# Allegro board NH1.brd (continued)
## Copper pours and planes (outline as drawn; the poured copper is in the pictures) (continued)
GND on TOP (solid shape): 11.15,53.3 11.2,53.27 11.27,53.21 11.48,53.01 11.5,53 11.63,52.85 11.57,52.66 11.53,52.63 11.53,52.35 11.61,52.27 11.61,52.11 11.5,52 11.5,51.66 12.14,51.02 12.17,51.01 12.24,50.96 12.28,50.89 12.3,50.86 12.3,50.85 12.54,50.61 12.58,50.55 12.59,50.49 12.58,50.43 12.55,50.38 12.54,50.37 12.49,50.34 12.44,50.33 12.38,50.32 12.17,50.12 12.17,50.04 12.11,49.96 12,49.99 11.96,50.03 11.96,50.29 12.02,50.59 11.76,50.77 11.22,50.77 11.05,50.93 11.01,51 10.97,51.06 10.93,51.14 10.97,51.21 11.08,51.48 10.93,51.72 10.93,51.72 10.74,51.91 10.74,52.4 10.85,52.52 10.87,52.52 11.07,52.78 10.92,53.08 10.93,53.11 10.94,53.19 10.97,53.24 11,53.27 11.05,53.3 11.1,53.31
GND on TOP (solid shape): 14.01,56.49 14.13,56.52 14.13,56.34 14.46,56.01 14.46,56 14.58,55.87 14.75,55.82 14.78,55.8 14.8,55.77 14.8,55.13 14.82,55.02 14.88,54.93 15.12,54.69 15.12,54.68 15.22,54.54 15.38,54.49 15.45,54.46 15.48,54.39 15.48,53.67 15.53,53.64 15.62,53.47 15.53,53.3 15.52,53.29 15.21,52.98 15.15,52.98 15.1,52.97 15.03,52.97 14.97,52.98 14.88,52.89 14.65,52.89 14.65,54.52 14.63,54.55 14.58,54.63 14.49,54.68 14.45,54.72 14.19,54.72 13.8,54.33 13.72,54.3 13.65,54.34 13.6,54.38 13.53,54.42 13.4,54.55 13.4,54.59 13.34,54.61 13.29,54.66 13.24,54.7 13.22,54.74 12.96,55 12.93,55.06 12.91,55.12 12.91,55.16 12.62,55.45 12.6,55.52 12.62,55.59 12.65,55.62 12.66,55.64 12.74,55.69 12.82,55.66 13.05,55.44 13.79,55.44 14.03,55.68 14.03,55.91 13.87,56.07 13.73,56.07 13.73,56.15 13.81,56.23 13.82,56.24 13.93,56.31 13.98,56.43
GND on TOP (solid shape): 26.25,63.36 26.26,63.36 26.37,63.25 27.25,63.25 27.41,63.1 27.41,62.97 27.46,62.82 27.61,62.77 27.91,62.77 27.95,62.77 27.99,62.78 28.09,62.78 28.14,62.69 28.14,62.08 27.55,61.5 27.54,61.49 27.38,61.41 27.29,61.25 27.29,61.24 27.22,61.16 27.15,61.13 27.08,61.16 26.58,61.04 26.9,60.64 26.92,60.64 27.02,60.54 27.02,60.2 26.92,59.95 27.02,59.7 27.02,59.54 26.92,59.44 26.01,59.44 25.84,59.61 25.84,59.63 25.76,59.87 25.55,59.99 25.29,59.94 25.14,59.73 25.14,59.58 25.19,59.44 25.19,59.34 25.11,59.29 24.53,59.29 24.48,59.34 24.48,60.3 24.63,60.46 25.13,60.46 25.77,61.1 25.77,61.82 26.09,62.13 26.26,62.13 26.4,62.19 26.46,62.33 26.46,62.61 26.45,62.66 26.44,62.7 26.36,62.79 26.26,62.82 25.96,62.82 25.93,62.81 25.9,62.81 25.48,62.81 25.4,62.9 25.4,63.35 25.7,63.66 25.95,63.66
GND on TOP (solid shape): 14.01,56.49 14.09,56.52 14.15,56.49 14.19,56.43 14.21,56.35 14.25,56.29 14.44,56.1 14.44,56.09 14.54,55.89 14.75,55.82 14.82,55.79 14.85,55.72 14.85,55.13 14.86,55.04 14.91,54.97 15.1,54.78 15.1,54.76 15.19,54.57 15.38,54.49 15.45,54.46 15.48,54.39 15.48,53.67 15.53,53.64 15.62,53.47 15.53,53.3 15.52,53.29 15.21,52.98 15.16,52.98 15.14,52.96 14.95,52.97 14.88,52.89 14.7,52.89 14.67,52.91 14.65,52.94 14.65,54.52 14.63,54.55 14.63,54.56 14.58,54.63 14.5,54.68 14.49,54.68 14.45,54.72 14.19,54.72 13.8,54.33 13.72,54.3 13.65,54.34 13.56,54.41 13.46,54.44 13.44,54.44 13.41,54.47 13.4,54.48 13.4,54.5 13.4,54.58 13.32,54.62 13.27,54.66 13.23,54.72 13.22,54.74 12.96,55 12.91,55.06 12.91,55.16 12.59,55.49 12.56,55.56 12.59,55.63 12.63,55.69 12.65,55.77 12.67,55.8 12.71,55.81 12.75,55.81 12.93,55.63 13.07,55.49 13.77,55.49 13.91,55.63 13.97,55.85 13.8,56.01 13.75,56.05 13.73,56.12 13.73,56.13 13.75,56.19 13.8,56.23 13.92,56.3 13.98,56.43
GND on TOP (solid shape): outline of 94 points within 7.09,58.43 10.99,66.74
GND on TOP (solid shape): outline of 268 points within 3.53,76.15 6.64,78.59
GND on TOP (solid shape): outline of 133 points within 5.91,54.29 10.65,57.14
GND on TOP (solid shape): outline of 687 points within 22.54,83.91 32.99,91.29
GND on TOP (solid shape): outline of 1494 points within 16.38,51.67 29.68,58.47
GND on TOP (solid shape): outline of 4116 points within 0.51,0.51 32.99,91.29
GND on TOP (solid shape): outline of 4131 points within 2.82,41.79 22.4,52.79
GND on BOTTOM (solid shape): 11.63,28.56 11.63,28.26 11.54,28.17 10.26,28.17 10.1,28.33 10.1,28.81 10.18,28.88 10.2,28.89 10.27,28.9 10.34,28.94 11.25,28.94
GND on BOTTOM (solid shape): 6.11,60.81 6.18,60.9 6.29,60.88 6.44,60.73 6.5,60.73 6.59,60.66 6.57,60.55 6.3,60.29 6.3,59.09 6.31,59.05 6.32,59.01 6.32,57.82 6.25,57.74 6.22,57.73 6.15,57.74 6.09,57.73 6,57.75 5.96,57.83 5.96,58.35 6.11,58.51
GND on BOTTOM (solid shape): 8.75,31.83 8.75,31.37 8.65,31.27 8.2,31.27 8.16,31.23 8.14,31.23 7.97,31.07 7.97,31.05 7.54,30.61 7.23,30.61 7.23,30.61 6.97,30.61 6.61,30.26 6.61,29 6.64,28.97 6.64,28.14 7.06,27.73 7.06,26.37 6.92,26.24 6.36,26.24 6.32,26.25 6.29,26.26 6.3,26.44 6.22,26.59 6.21,26.62 6.31,26.88 6.21,27.13 6.22,27.17 6.28,27.51 5.98,27.69 5.94,27.69 5.9,27.69 5.82,27.71 5.79,27.79 5.34,28.23 5.34,30.46 5.01,30.79 5.01,31.5 5.24,31.73 7.14,31.73 7.19,31.68 7.19,31.67 7.35,31.5 7.71,31.5 8.11,31.91 8.67,31.91
GND on BOTTOM (solid shape): 8.15,69.21 8.17,69.2 8.18,69.18 8.21,69.01 8.33,68.88 8.33,68.69 8.24,68.6 8.24,68.44 8.23,68.31 8.28,68.19 8.28,63.76 8.22,63.7 8.17,63.62 8.15,63.54 8.15,63.38 7.99,63.38 7.91,63.36 7.83,63.31 7.73,63.21 7.69,63.14 7.67,63.05 7.67,62.89 7.51,62.89 7.42,62.88 7.35,62.83 7.25,62.73 7.2,62.65 7.18,62.57 7.18,62.41 7.02,62.41 6.94,62.39 6.86,62.34 6.76,62.24 6.71,62.17 6.7,62.08 6.7,61.92 6.54,61.92 6.45,61.91 6.38,61.86 6.28,61.76 6.23,61.68 6.21,61.6 6.21,61.44 6.05,61.44 5.97,61.42 5.89,61.37 5.72,61.2 5.72,60.02 5.64,59.94 5.42,59.94 5.36,60 5.36,61.03 7.92,63.58 7.92,69.12 8,69.21
GND on BOTTOM (solid shape): 18.75,21.49 18.83,21.45 18.85,21.36 18.85,21.15 18.99,21 19.02,20.98 19.02,20.4 18.93,20.31 18.93,20.21 18.85,20.21 18.85,19.86 18.72,19.86 18.61,19.83 18.54,19.75 18.52,19.71 18.52,19.66 18.52,19.38 18.54,19.29 18.6,19.22 18.65,19.13 18.6,19.05 18.54,18.98 18.52,18.88 18.52,18.6 18.57,18.46 18.72,18.4 18.85,18.4 18.85,18.05 18.98,18.05 19.06,17.97 18.06,16.97 18.06,16.63 18.06,14.44 18.7,13.79 18.7,13.32 18.66,13.31 18.49,13.23 18.4,13.05 18.37,12.99 18.23,13 18.2,13.07 18.05,13.33 17.75,13.33 17.65,13.34 17.6,13.42 17.6,13.75 15.5,13.75 15.4,13.85 15.4,14.41 15.5,14.51 17.23,14.51 17.38,14.66 17.38,21.11 17.77,21.49
GND on BOTTOM (solid shape): 32.99,89.59 32.99,84.47 32.89,84.44 32.83,84.41 32.73,84.42 32.69,84.51 32.69,87.01 31.93,87.77 31.91,87.85 31.97,87.92 32.13,88.14 32.05,88.41 32.02,88.48 32.05,88.55 32.07,88.95 31.67,89.02 31.47,89.22 31.47,89.73 31.58,90.07 31.29,90.28 31.27,90.28 31.03,90.52 28.64,90.52 28.37,90.25 27.49,90.25 27.04,90.71 26.07,90.71 25.56,90.69 25.77,90.23 25.82,90.22 25.82,88.83 25.61,88.63 25.06,88.63 25.05,88.62 24.7,88.38 24.94,88.02 25.02,87.95 24.99,87.85 24.83,87.69 21.68,87.69 21.35,88.02 20.84,88.02 20.48,88.37 20.48,91.24 20.53,91.29 31.29,91.29
GND on BOTTOM (solid shape): outline of 150 points within 30.13,73.81 32.24,82.68
GND on BOTTOM (solid shape): 31.1,72.76 31.17,72.86 31.28,72.83 31.66,72.63 32.09,72.72 32.19,72.72 32.24,72.63 32.24,54.5 32.44,53.9 32.96,53.53 32.99,53.52 32.99,28.43 32.69,28.12 32.58,28.12 32.42,28.28 32.42,30.26 26.42,30.26 26.42,26.7 26.26,26.53 25.7,26.53 25.59,26.65 25.59,30.38 28.12,32.92 28.12,36.1 31.02,39 31.11,39.03 31.18,38.97 31.89,38.64 32.38,39.25 32.38,40.75 31.75,41.38 31.12,40.75 31.12,40.29 31.06,40.19 30.95,40.22 30.27,40.89 30.27,41.3 30.29,41.33 30.31,41.33 30.64,41.68 30.33,42.04 30.31,42.04 30.27,42.09 30.27,43.67 30.31,43.72 30.69,43.72 30.97,44 30.97,46.69 31.66,47.38 31.66,62.59 31.1,63.15
GND on BOTTOM (solid shape): outline of 176 points within 26.35,53.96 28.81,56.41
GND on BOTTOM (solid shape): outline of 351 points within 22.79,58.28 28.65,62.93
GND on BOTTOM (solid shape): outline of 108 points within 24.76,53.28 28.84,57.89
GND on BOTTOM (solid shape): outline of 3191 points within 0.51,0.51 32.99,91.29
GND on GND (solid shape): outline of 17446 points within 0.51,0.51 32.99,91.29
GND on IN1 (solid shape): 6.21,45.44 6.21,40.68 5.82,40.29 5.63,40.29 5.56,40.37 5.56,41.38 4.13,42.81 4.13,45.55 4.51,45.94 5.72,45.94
GND on IN1 (solid shape): 5.77,60.81 5.77,60.69 5.8,60.65 5.8,58.83 6.5,58.14 6.5,58.07 6.51,58.01 6.51,57.99 6.49,57.98 6.08,57.98 5.37,58.69 5.37,60.85 5.47,60.95 5.63,60.95
GND on IN1 (solid shape): 7.39,45.05 7.46,45.14 7.57,45.12 9.48,43.21 9.97,43.21 10.15,43.11 10.35,43.15 10.45,43.15 10.5,43.06 10.5,39.53 10.25,39.27 8.12,39.27 7.39,40
GND on IN1 (solid shape): 7.79,71.22 7.8,71.19 7.9,70.86 8.25,70.84 8.28,70.84 8.29,70.82 8.29,68.17 8.27,68.15 8.25,68.15 8.13,68.27 7.55,68.27 7.55,70.38 7.65,70.66 7.47,70.89 7.45,70.9 7.46,70.93 7.76,71.23
GND on IN1 (solid shape): 26.85,60.1 26.92,60.07 26.95,59.99 27.26,59.62 27.61,59.95 28.39,59.95 28.97,59.37 28.97,56.78 28.91,56.69 28.81,56.7 28.73,56.73 28.64,56.75 28.62,56.75 28.1,57.26 28.1,57.66 27.91,57.85 27.91,57.87 26.31,59.47 26.31,59.85 26.56,60.1
GND on IN1 (solid shape): 15.31,24.73 15.31,24.17 15.17,24.03 14.54,24.03 14.3,24.27 14.3,24.29 14.31,24.33 14.38,24.4 14.39,24.52 14.38,24.63 14.31,24.71 14.22,24.79 14.11,24.8 14,24.79 13.91,24.71 13.86,24.65 13.76,24.55 13.76,24.05 14.32,23.5 15.53,23.5 15.73,23.29 15.73,22.51 15.56,22.33 14.33,22.33 14.1,22.1 12.43,22.1 12.09,22.45 12.09,24.78 12.56,25.25 14.79,25.25
GND on IN1 (solid shape): 2.78,17.36 2.84,17.45 2.95,17.43 3.49,16.89 3.51,16.85 3.44,16.62 3.53,16.44 3.56,16.36 3.53,16.29 3.44,16.04 3.59,15.83 3.59,15.42 4.05,14.96 4.05,14.16 4.01,14.07 3.91,14.06 3.88,14.07 3.83,14.08 2.78,15.13
GND on IN1 (solid shape): 8.74,54.5 8.88,54.35 8.88,54.05 8.54,53.71 8.54,53.7 8.5,53.65 8.47,53.6 7.25,52.38 7.25,52.36 7.24,52.34 7.26,51.9 7.7,51.95 7.78,51.99 7.86,51.95 8.02,51.84 8.21,51.84 8.24,51.85 8.34,51.74 8.34,51.54 8.16,51.35 7.54,51.35 7.17,51.71 6.29,51.71 6.01,52 6.01,53.51 6.59,54.09 6.83,54.09 6.99,53.93 7.23,53.93 7.66,53.91 7.68,54.34 7.66,54.45 7.75,54.51 8.67,54.51
GND on IN1 (solid shape): outline of 120 points within 6.51,45.85 9.87,49.31
GND on IN1 (solid shape): outline of 129 points within 21.03,53.99 23.77,55.83
GND on IN1 (solid shape): 26.31,67.82 26.35,67.91 26.44,67.92 26.5,67.9 26.55,67.9 26.82,67.9 27.12,67.6 27.12,67.05 26.95,66.89 26.95,63.98 26.9,63.89 26.8,63.9 26.29,63.62 26.8,63.34 26.9,63.34 26.95,63.25 26.95,61.36 26.87,61.27 26.85,61.27 26.67,61.21 26.56,61.05 26.54,61.02 25.09,61.02 24.58,60.51 21.15,57.08 21.04,57.08 21.03,57.08 19.26,57.08 19.06,57.27 19.06,58.19 19.25,58.38 19.29,58.45 19.36,58.47 19.4,58.47 19.67,58.2 21.53,58.2 25.44,62.1 25.44,65.53 25.61,65.7 25.69,65.73 25.77,65.69 26.28,65.63 26.23,66.15 26.18,66.22 26.21,66.3 26.31,66.4
GND on IN1 (solid shape): outline of 429 points within 10.92,86.09 21.11,89.72
GND on IN1 (solid shape): outline of 3887 points within 0.51,0.51 32.99,91.29
GND on IN1 (solid shape): outline of 5541 points within 2.09,54.6 26.61,86.11
GND on IN2 (solid shape): 26.48,29.95 26.48,26.75 26.22,26.5 25.92,26.5 25.77,26.65 25.77,29.9 25.99,30.13 26.3,30.13
GND on IN2 (solid shape): 7.58,85.37 7.58,85.17 7.53,85.12 7.03,85.12 5.06,83.15 5.06,82.11 5.03,82.07 4.98,82.08 4.9,82.15 4.8,82.15 4.62,82.05 4.61,81.86 4.43,81.56 4.25,81.86 4.24,82.05 4.07,82.15 3.45,82.15 2.89,81.6 2.79,81.58 2.73,81.67 2.73,83.94 4.34,85.55 7.4,85.55
GND on IN2 (solid shape): 14.58,73.16 15.56,73.16 15.68,73.27 15.69,73.27 15.86,73.28 16,73.39 16.47,73.39 16.53,73.4 16.58,73.43 16.71,73.56 16.71,73.84 18.34,73.84 19.15,73.03 19.42,73.03 19.68,72.77 20.28,72.77 20.97,73.46 21.94,73.46 21.96,73.45 21.96,73.43 21.95,73.39 21.93,73.34 21.13,73.34 20.15,72.37 19.42,72.37 19.19,72.6 19.19,72.75 18.25,73.69 17.1,73.69 15.13,71.72 13.38,71.72 13.36,71.73 13.36,71.76 13.42,71.98 13.3,72.18 13.29,72.2 13.3,72.22 13.66,72.58 13.66,73.22 13.26,73.62 11.78,73.62 11.17,73.01 11.14,73.01 11.13,73.04 10.77,73.39 10.57,72.93 10.57,72.9 10.55,72.89 10.27,72.89 9.87,72.49 9.87,72.12 9.81,72.06 8.75,72.06 8.68,72.13 8.68,72.76 8.67,72.78 8.67,73.25 8.82,73.4 9.94,73.4 10.49,73.95 10.52,73.95 10.54,73.93 10.94,73.6 11.05,74.1 11.05,74.13 11.07,74.15 13.59,74.15
GND on IN2 (solid shape): 17.47,73.1 17.49,73.08 17.49,73.06 17.45,72.97 17.43,72.86 13.55,68.97 13.55,62.25 13.54,62.23 13.51,62.23 13.11,62.05 13.31,61.65 13.33,61.63 13.31,61.61 13.13,61.22 13.51,61.03 13.54,61.03 13.55,61.01 13.55,60.41 13.04,59.9 13.04,56.7 12.96,56.62 12.39,56.62 12.37,56.63 12.37,56.66 12.35,56.97 12.06,57.1 12.04,57.12 12.04,57.15 12.65,57.75 12.65,69.16 12.66,69.18 12.69,69.18 13.16,69.51 12.58,69.54 12.56,69.52 12.54,69.53 11.39,70.68 11.39,71.84 11.15,72.08 11.14,72.18 11.11,72.26 11.11,72.28 11.13,72.3 11.29,72.3 12.02,73.03 13.01,73.03 13.07,72.98 13.07,72.82 13,72.76 12.14,72.76 11.57,72.19 11.57,71.53 11.96,71.14 12.22,71.14 12.22,71.13 12.52,70.84 12.83,71.12 12.83,71.13 15.38,71.13 17.35,73.1
GND on IN2 (solid shape): 4.46,67.65 4.57,67.63 6.74,65.45 6.74,64.98 6.77,64.95 6.77,64.68 6.75,64.63 6.74,64.58 6.74,64.45 6.75,64.4 6.77,64.35 6.77,64.07 6.75,64.02 6.74,63.97 6.74,61 7.93,59.8 7.96,59.73 7.93,59.66 7.9,59.63 7.88,59.6 7.79,59.56 7.71,59.6 7.25,59.63 7.28,59.17 7.32,59.09 7.28,59.01 7.25,58.98 7.22,58.95 7.14,58.91 7.06,58.95 6.59,58.99 6.63,58.52 6.68,58.44 6.63,58.36 6.5,58.14 6.57,57.91 6.59,57.8 6.5,57.74 6.21,57.74 6.15,57.74 6.11,57.74 5.62,57.74 5.44,57.92 4.35,57.92 4.35,57.96 4.29,58.09 4.18,58.18 4.13,58.25 4.15,58.34 4.62,58.81 4.68,58.9 4.68,59 4.68,59.01 4.68,61.9 4.68,61.96 4.68,66.81 4.28,67.2 4.26,67.28 4.29,67.35 4.36,67.45 4.39,67.56
GND on IN2 (solid shape): outline of 197 points within 28.31,81.24 30.82,86.11
GND on IN2 (solid shape): outline of 291 points within 6.88,30.74 17.15,35.82
GND on IN2 (solid shape): outline of 768 points within 20.53,71.9 26.08,84.72
GND on IN2 (solid shape): outline of 5271 points within 0.51,0.51 32.99,91.29
GND on VCC (solid shape): outline of 15519 points within 0.51,0.51 32.99,91.29
+V_IPSOUT on TOP (solid shape): 9.56,26.45 9.56,25.89 9.26,25.58 8.6,25.58 8.34,25.84 8.34,26.19 8.75,26.6 9.41,26.6
+V_IPSOUT on TOP (solid shape): 12.91,26.75 12.91,26.4 12.63,26.12 12.63,25.15 12.58,25.1 12.1,25.1 12.05,25.15 12.05,26.07 12.02,26.09 12.02,26.52 12.41,26.9 12.76,26.9
+V_IPSOUT on TOP (solid shape): 23.92,22.2 25.41,22.2 25.41,21.84 24.02,21.84 24.02,21.55 25.41,21.55 25.41,21.19 23.74,21.19 23.56,21.01 21.24,21.01 21.12,21.14 21.12,21.8 21.35,22.03 21.6,22.03 22.31,22.74 23.38,22.74
+V_IPSOUT on TOP (solid shape): 20.25,38.84 20.25,36.66 18.83,35.23 17.18,35.23 17.08,35.13 17.08,35.03 17.07,35.02 17.05,35.02 17.05,34.23 16.95,34.13 16.85,34.24 16.85,35.13 16.65,35.13 16.65,34.24 16.55,34.13 16.45,34.23 16.45,35.27 16.57,35.39 16.57,35.79 16.67,35.9 17.74,35.9 17.89,36.05 17.89,38.69 18.17,38.97 20.13,38.97
+V_IPSOUT on TOP (solid shape): 20.74,28.89 20.74,27.56 20.63,27.46 19.92,27.46 19.77,27.61 19.52,27.61 19.11,28.03 17.86,28.03 17.76,28.13 17.86,28.23 18.75,28.23 18.75,28.43 17.86,28.43 17.76,28.53 17.86,28.63 18.76,28.63 18.76,28.83 17.86,28.83 17.76,28.93 17.86,29.03 18.65,29.03 19.01,29.03 20.59,29.03
+V_IPSOUT on TOP (solid shape): 16.85,26.02 16.95,26.12 17.05,26.02 17.05,25.18 17.59,24.64 18.3,24.64 18.73,24.21 18.96,23.98 18.96,21.76 18.61,21.42 18.54,21.41 18.49,21.38 18.38,21.3 18.33,21.17 18.32,21.13 18.19,21.14 18.12,21.13 18.04,21.14 17.97,21.13 17.57,21.13 17.49,21.21 17.49,22.03 17.66,22.2 17.66,23.75 17.61,23.89 17.48,23.95 17.44,23.96 17.41,23.96 17.17,23.96 16.85,24.29
+V_IPSOUT on TOP (solid shape): 11.11,36.61 11.11,36.12 11.85,35.39 11.85,34.22 11.68,34.22 11.65,34.24 11.65,35.03 11.34,35.34 10.7,35.34 10.7,35.35 10.49,35.56 10.5,35.59 10.11,35.94 9.97,35.44 9.97,35.34 10.22,35.08 10.22,34.22 10.17,34.17 9.99,34.17 9.92,34.2 9.89,34.27 9.79,34.56 9.52,34.7 9.5,34.7 9.45,34.75 9.45,34.82 9.36,34.91 9.36,34.93 9.27,35.14 9.07,35.24 9.05,35.24 8.35,35.94 8.35,36.72 8.49,36.86 10.86,36.86
+V_IPSOUT on BOTTOM (solid shape): outline of 216 points within 6.77,26.29 14.11,31.83
+V_IPSOUT on IN1 (solid shape): 20.74,28.53 20.74,26.75 18.96,24.97 18.96,23.93 18.65,23.63 17.31,23.63 16.77,24.16 16.77,24.87 16.48,25.16 16.48,27.68 17.51,28.71 20.56,28.71
+V_IPSOUT on VCC (solid shape): outline of 1896 points within 8.04,21.29 31.46,90
+V_VBUS on TOP (solid shape): 16.47,36.81 16.47,35.49 16.25,35.27 16.25,34.3 16.2,34.24 16.08,34.24 16.05,34.27 16.05,35.15 15.61,35.59 15.61,36.1 15.81,36.3 15.81,36.86 15.96,37.01 16.27,37.01
+V_VBUS on TOP (solid shape): 26.22,34.78 26.22,33.71 26.99,32.95 29.42,32.95 29.53,32.85 29.53,31.98 27.67,30.13 27.67,29.62 27.34,29.29 26.63,29.29 26.48,29.44 26.48,29.75 26.25,29.98 25.79,29.98 25.72,30.05 25.72,32.34 25.46,32.59 25.46,35.08 25.61,35.23 25.77,35.23
+V_VBUS on TOP (solid shape): 21.79,36.99 21.79,35.46 21.46,35.13 20.08,35.13 19.87,34.93 19.87,33.61 19.09,32.83 17.86,32.83 17.76,32.93 17.86,33.03 18.68,33.03 18.91,33.25 18.91,35.13 20.36,36.59 20.36,36.83 20.62,37.09 21.69,37.09
+V_VBUS on BOTTOM (solid shape): outline of 305 points within 10.58,32.35 20.36,36.68
+V_VBUS on IN1 (solid shape): 26.32,38.71 26.91,38.71 28.31,37.32 28.31,33.61 27.9,33.2 25.66,33.2 25.41,33.46 25.41,34.98 25.92,35.49 25.92,35.95 26.22,36.25 26.22,36.74 25.96,36.99 25.85,36.99 25.84,37.04 25.66,37.28 25.37,37.22 25.34,37.25 24.49,37.25 23.9,36.65 23.89,36.65 22.07,34.83 21.7,34.83 20.28,33.41 16.52,33.41 15.74,34.19 15.74,36.43 16.11,36.81 18.5,36.81 19.06,36.25 19.42,36.25 20.85,37.68 20.88,37.67 21.17,37.74 21.23,38.03 21.22,38.06 22.03,38.87 26.17,38.87
+V_VCC on TOP (solid shape): 16.06,22.03 16.06,19.69 16.32,19.44 16.32,17.51 16.24,17.43 14.87,17.43 14.64,17.66 14.64,18.48 13.52,19.6 13.52,20.4 13.37,20.55 12.23,20.55 12.1,20.68 12.1,21.95 12.23,22.08 16.01,22.08
+V_VCC on TOP (solid shape): outline of 99 points within 8.95,52.28 14.55,55.27
+V_VCC on GND (solid shape): outline of 2878 points within 1.28,18.04 15.68,54.89
+V_VCC_LX on TOP (solid shape): 13.25,26.02 13.35,26.12 13.45,26.02 13.45,25.23 13.45,25.21 13.44,25.19 13.52,25.11 13.52,24.57 13.88,24.21 13.96,24.21 14.11,24.06 14.11,23.35 13.96,23.2 12.09,23.2 12.03,23.26 12.03,24.17 12.76,24.9 12.76,25.15 12.85,25.23 12.85,26.02 12.95,26.12 13.05,26.02 13.05,25.13 13.25,25.13
+V_VNN on TOP (solid shape): 23.91,30.97 23.91,28.79 24.22,28.49 24.22,25.34 23.8,24.92 23.27,24.92 23.09,25.11 22.81,25.11 22.62,24.92 22.62,24.81 22.54,24.73 21.68,24.73 21.5,24.91 21.5,27.01 22.06,27.56 22.06,28.43 21.85,28.63 21.61,28.63 21.5,28.74 21.5,30.97 21.63,31.09 23.78,31.09
+V_VNN on TOP (solid shape): 12.58,52.56 12.65,52.52 12.74,52.51 12.76,52.5 12.82,52.43 12.83,52.42 12.99,52.23 13.25,52.26 13.59,52.26 13.7,52.17 13.78,52.09 13.79,52.07 13.83,51.98 13.9,51.9 13.95,51.82 13.9,51.73 13.79,51.39 14.09,51.18 14.11,51.18 14.16,51.13 14.16,51.12 14.2,51.02 14.27,50.94 14.29,50.92 14.29,50.71 14.2,50.63 14.16,50.52 14.14,50.48 14.1,50.46 14.08,50.46 13.87,50.38 13.77,50.17 13.77,50.15 13.73,50.11 13.71,50.1 13.49,49.91 13.56,49.62 13.6,49.58 13.63,49.5 13.59,49.42 13.48,49.31 13.45,49.16 13.45,48.87 13.4,48.82 12.89,48.82 12.68,49.04 12.69,49.07 12.7,49.22 12.62,49.36 12.38,49.61 12.33,49.69 12.28,49.74 12.28,50.08 12.42,50.22 12.44,50.22 12.62,50.31 12.69,50.49 12.67,50.59 12.62,50.68 12.4,50.89 12.4,50.9 12.38,50.92 12.38,50.93 12.31,51.04 12.2,51.11 12.19,51.11 11.65,51.66 11.6,51.71 11.6,51.95 11.83,52.18 11.91,52.18 12.3,52.56
+V_VNN on TOP (solid shape): outline of 119 points within 14.39,49.97 17.87,55.91
+V_VNN on IN2 (solid shape): outline of 1435 points within 12.56,25.13 23.25,55.89
+V_VNN on VCC (solid shape): outline of 148 points within 13.78,49.26 16.47,51.85
+V_VNN_PH1_LX on TOP (solid shape): 19.43,27.46 19.72,27.46 20.33,26.85 20.58,26.85 20.74,26.7 20.74,24.82 20.63,24.72 19.77,24.72 19.36,25.13 19.36,26.51 18.65,27.23 17.86,27.23 17.76,27.33 17.86,27.43 18.76,27.43 18.76,27.63 17.86,27.63 17.76,27.73 17.86,27.83 19.06,27.83
+V_VNN_PH2_LX on TOP (solid shape): 20.69,31.12 20.69,29.34 20.53,29.19 19.67,29.19 19.21,29.65 18.71,29.65 18.68,29.63 18.65,29.63 17.86,29.63 17.76,29.73 17.86,29.83 18.81,29.83 18.81,30.03 17.86,30.03 17.76,30.13 17.86,30.23 18.65,30.23 18.65,30.24 19.2,30.24 19.72,30.76 19.72,31.17 19.77,31.22 20.59,31.22
+V_VTT on TOP (solid shape): 7.55,32.73 7.55,32.45 7.55,32.44 7.58,32.16 7.83,32.03 7.88,31.98 8.04,31.98 8.6,31.42 8.6,31.17 8.54,31.12 8.39,31.12 8.02,31.49 8.02,31.55 7.96,31.55 7.83,31.68 7.22,31.68 7.07,31.83 7.07,32.75 7.12,32.8 7.48,32.8
+V_VTT on BOTTOM (solid shape): 9.15,85.88 9.15,85.58 9.41,85.32 9.41,84.44 9.15,84.18 8.32,84.18 8.04,84.46 8.04,85.48 8.34,85.78 8.5,85.78 8.65,85.93 9.1,85.93
+V_VTT on IN2 (solid shape): 9.15,85.88 9.15,85.73 8.6,85.17 7.94,85.17 7.22,85.88 7.22,86.03 7.27,86.09 8.95,86.09
+VSDIO on TOP (solid shape): 16.28,10.56 15.82,10.56 15.82,10.37 16.28,10.37 16.28,10.16 15.48,10.16 15.35,10.04 14.89,10.04 14.89,10.6 15.06,10.77 16.28,10.77
+VSDIO1 on BOTTOM (solid shape): 2.8,28.58 2.8,27.11 2.6,26.9 2.3,26.9 2.14,27.06 2.14,28.58 2.3,28.73 2.65,28.73
V_USB on TOP (solid shape): 5.9,35.9 5.9,35.48 5.56,35.13 4.02,35.13 3.97,35.18 3.97,36 4.63,36.66 5.14,36.66
V_USB on TOP (solid shape): outline of 260 points within 17.54,12.65 31,28.28
V_USB on BOTTOM (solid shape): 28.81,22.74 28.81,19 28.61,18.8 27.73,18.8 27.52,18.88 27.32,18.8 25.13,18.8 24.95,18.98 24.95,19.92 25.08,20.05 25.69,20.05 26.32,20.68 26.32,22.71 26.58,22.97 28.59,22.97
V_USB on IN1 (solid shape): outline of 363 points within 3.13,17.71 6.77,36.96
V_USB on VCC (solid shape): outline of 384 points within 2.45,11.87 28.71,20.3
N16996868 on BOTTOM (solid shape): 8.39,33.86 8.39,33.05 8.04,32.69 7.73,32.69 7.22,32.19 5.5,32.19 5.14,32.54 5.14,33.19 5.22,33.27 5.62,33.27 5.63,33.27 5.86,33.27 5.95,33.25 6.08,33.27 6.08,33.27 7.14,33.27 7.91,34.04 8.21,34.04

Small or netless copper shapes (teardrops, artwork), in the pictures only: 30 on TOP, 12 on BOTTOM, 1 on GND, 2 on IN1, 2 on IN2, 3 on VCC

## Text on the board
Ref Des/Silkscreen Bottom: REV:C | DA0NH1MB6C0
User.Comments: A | M | B | N | C | P | D | R | E | T | 2 | 1 | 3D | 3B | 3C | SDTF | HDMI_SL | PMIC | PCB EDGE | PCB BOARD EDGE | SPI | WI5BT | 20.0x79.0 | 91.80 | 33.50
Ref Des/Silkscreen Top: DA0NH1MB6C0 | REV:C
GND: GND | 2
VCC: VCC | 5
PAGE_OUTLINE: (3489.9MIL) | 88.64 | (1290MIL) | 32.77 | 33.50 | 82.50
User.45: FIGURE | TYPE | Oblong | Circle | SIZE | 43.0x28.0 | 98.0x35.0 | 79.0x20.0 | 8.0 | 10.0 | 12.0 | 14.0 | 31.0 | 36.0 | 71.0 | 35.0 | 87.0 | DRILL CHART: TOP to BOTTOM | ALL UNITS ARE IN MILS | PLATED | NON-PLATED | ROTATION | 0.000 | 90.000 | - | QTY | 4 | 2 | 3 | 1 | 10 | 896 | 55 | 8 | 25 | 994 | TOTAL HOLES:
